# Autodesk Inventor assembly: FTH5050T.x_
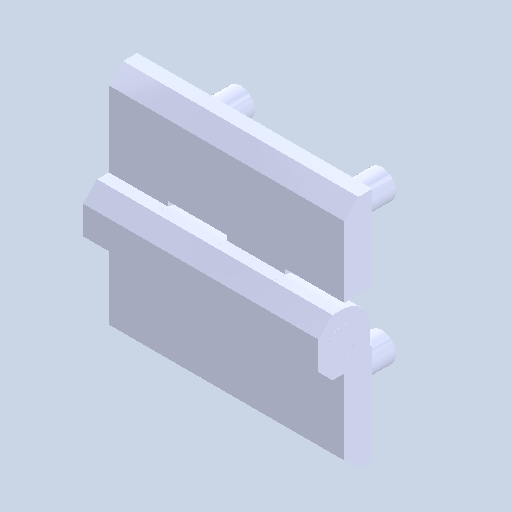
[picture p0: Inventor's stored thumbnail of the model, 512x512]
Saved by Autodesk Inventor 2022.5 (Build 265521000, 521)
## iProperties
Created: 2024-08
Part Number: FTH5050T.x_
Document SubType Name: Assembly
Designer: ImaoCorp
Author: ImaoCorp
Sending System: SOLIDWORKS 2022-2022290
MC: AMD64
MC_MODEL: Intel64 Family 6 Model 60 Stepping 3, GenuineIntel
OS: Windows_NT
FRU: Parasolid Version 33.1, build 260,  4-25-2022
FORMAT: text
GUISE: transmit
KEY: FILEFTH5050T.x_t
DATE: Mon Aug  5 14:46:40 2024
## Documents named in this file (4)
- Y:\5.更新分\2024年対応\0805_FTH\fth5050t\FTH5050T.x_.iam
- Y:\5.更新分\2024年対応\0805_FTH\fth5050t\FTH5050T_01.ipt
- Y:\5.更新分\2024年対応\0805_FTH\fth5050t\FTH5050T_02.ipt
- Y:\5.更新分\2024年対応\0805_FTH\fth5050t\FTH5050T_03.ipt
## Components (3 placed, 3 different names)
1. FTH5050T_01
2. FTH5050T_02
3. FTH5050T_03
